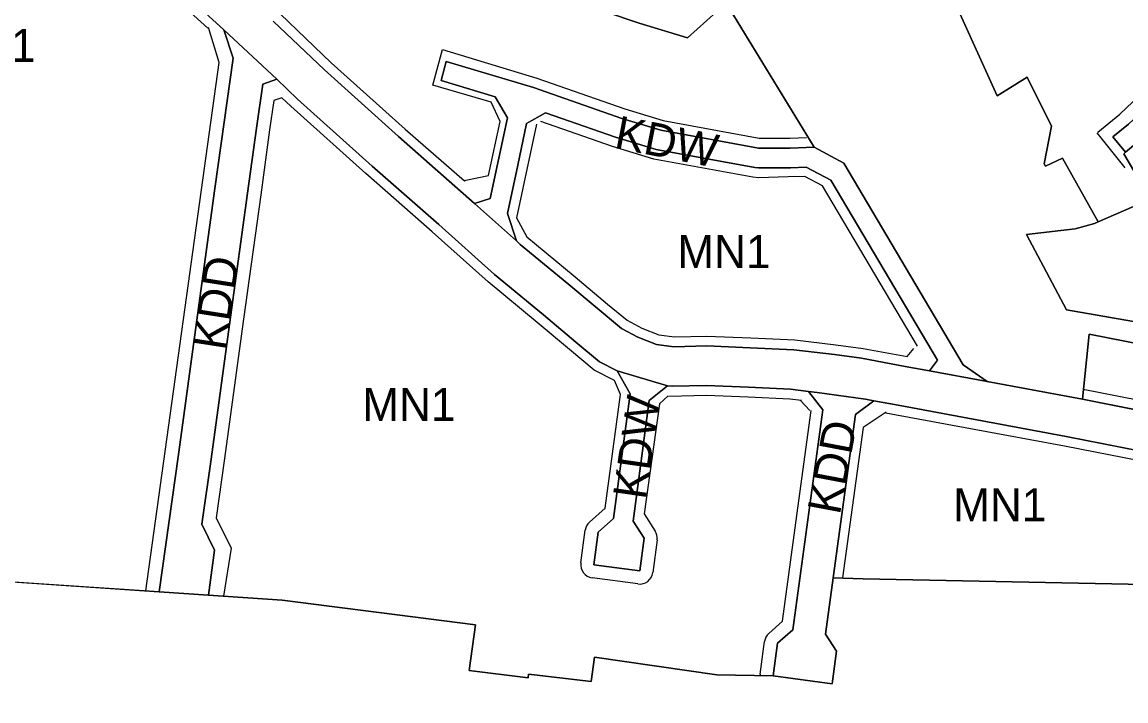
# Model space of a CAD drawing. Extents: x 7417187 to 7419415, y 5539178 to 5540826.
# Drawn here: x 7418400.2 to 7418734.7, y 5539565.4 to 5539771.1 of the extents above; entities that cross this region are included whole.
import ezdxf

# ---------------------------------------------------------------- set-up
doc = ezdxf.new("R2010")
doc.units = 0
for name, color, linetype in [('linie_rozgraniczajace', 7, 'Continuous'), ('linie_zabudowy_nieprzekraczalne', 7, 'Continuous'), ('linie_zabudowy_obowiazujace', 7, 'Continuous'), ('oznaczenia_przeznaczen', 7, 'Continuous')]:
    doc.layers.add(name, color=color, linetype=linetype)

msp = doc.modelspace()

# ---------------------------------------------------------------- linework, layer by layer
at = {"layer": 'linie_rozgraniczajace'}
for p, q in [((7418461.39, 5539768.7), (7418451.14, 5539778.14)), ((7418476.33, 5539771.33), (7418491.86, 5539756.55)), ((7418477.41, 5539753.73), (7418461.39, 5539768.7)), ((7418491.86, 5539756.55), (7418514.31, 5539736.4)), ((7418483.71, 5539747.74), (7418477.41, 5539753.73)), ((7418506.34, 5539727.43), (7418483.71, 5539747.74)), ((7418514.31, 5539736.4), (7418537.33, 5539716.11)), ((7418526.49, 5539709.72), (7418506.34, 5539727.43)), ((7418537.33, 5539716.11), (7418550, 5539704.75)), ((7418543.36, 5539694.58), (7418526.49, 5539709.72)), ((7418550, 5539704.75), (7418551.18, 5539703.68)), ((7418551.18, 5539703.68), (7418565.9, 5539691.58)), ((7418558.2, 5539682.36), (7418543.36, 5539694.58)), ((7418565.9, 5539691.58), (7418581.85, 5539678.19)), ((7418567.96, 5539674.1), (7418558.2, 5539682.36)), ((7418581.85, 5539678.19), (7418586.77, 5539675.61)), ((7418575.18, 5539668.14), (7418567.96, 5539674.1)), ((7418586.77, 5539675.61), (7418592.44, 5539673.34)), ((7418592.44, 5539673.34), (7418597.74, 5539672.7)), ((7418597.74, 5539672.7), (7418607.68, 5539672.92)), ((7418607.68, 5539672.92), (7418620.86, 5539672.39)), ((7418620.86, 5539672.39), (7418634.07, 5539671.76)), ((7418634.07, 5539671.76), (7418646.4, 5539670.32)), ((7418646.4, 5539670.32), (7418654.54, 5539669.18)), ((7418580.51, 5539665.34), (7418575.18, 5539668.14)), ((7418654.54, 5539669.18), (7418667.82, 5539666.74)), ((7418667.82, 5539666.74), (7418675.19, 5539665.37)), ((7418595.74, 5539660.85), (7418580.51, 5539665.34)), ((7418675.19, 5539665.37), (7418692.57, 5539662.15)), ((7418597.15, 5539660.69), (7418595.74, 5539660.85)), ((7418607.57, 5539660.91), (7418597.15, 5539660.69)), ((7418620.34, 5539660.4), (7418607.57, 5539660.91)), ((7418633.08, 5539659.8), (7418620.34, 5539660.4)), ((7418638.52, 5539659.16), (7418633.08, 5539659.8)), ((7418692.57, 5539662.15), (7418718.81, 5539657.28)), ((7418641.12, 5539658.85), (7418638.52, 5539659.16)), ((7418655.74, 5539656.76), (7418641.12, 5539658.85)), ((7418658.31, 5539656.29), (7418655.74, 5539656.76)), ((7418665.64, 5539654.94), (7418658.31, 5539656.29)), ((7418718.81, 5539657.28), (7418721.47, 5539656.75)), ((7418721.47, 5539656.75), (7418755.04, 5539650.17)), ((7418716.56, 5539645.49), (7418665.64, 5539654.94)), ((7418743.77, 5539640.15), (7418716.56, 5539645.49)), ((7418643.64, 5539585.58), (7418645.97, 5539602.68)), ((7418645.97, 5539602.68), (7418655.08, 5539602.38)), ((7418379.39, 5539602.6), (7418441.73, 5539598.41)), ((7418655.08, 5539602.38), (7418740.36, 5539600.67)), ((7418441.73, 5539598.41), (7418456.67, 5539597.41)), ((7418456.67, 5539597.41), (7418479.05, 5539595.91)), ((7418479.05, 5539595.91), (7418537.63, 5539588.41)), ((7418537.63, 5539588.41), (7418535.64, 5539574.6)), ((7418646.97, 5539580.4), (7418643.64, 5539585.58)), ((7418645.63, 5539570.49), (7418646.97, 5539580.4)), ((7418572.64, 5539571.27), (7418573.63, 5539578.64)), ((7418573.63, 5539578.64), (7418610.7, 5539573.29)), ((7418535.64, 5539574.6), (7418553.6, 5539572.38)), ((7418553.6, 5539572.38), (7418553.71, 5539573.49)), ((7418553.71, 5539573.49), (7418572.64, 5539571.27)), ((7418610.7, 5539573.29), (7418627.79, 5539572.92)), ((7418627.79, 5539572.92), (7418645.63, 5539570.49))]:
    msp.add_line(p, q, dxfattribs=at)
for points in [[(7418393.93, 5539842.31), (7418427.7, 5539802.79), (7418451.14, 5539778.14), (7418461.39, 5539768.7), (7418464.15, 5539760.11), (7418458.68, 5539720.6), (7418453.49, 5539682.96), (7418447.59, 5539640.03), (7418441.73, 5539598.41), (7418379.39, 5539602.6)], [(7418736.92, 5539715.13), (7418726.22, 5539710.49), (7418715.48, 5539729.82), (7418710.25, 5539727.38), (7418709.84, 5539728.16), (7418712.08, 5539739.56), (7418704.78, 5539754.37), (7418695.68, 5539748.68), (7418682.41, 5539778.05), (7418644.96, 5539813.17), (7418657.8, 5539827.5), (7418672.39, 5539827.92), (7418675.97, 5539823.68), (7418689.24, 5539814.6), (7418710.86, 5539804.53), (7418718.37, 5539803.19), (7418732.26, 5539794.78), (7418747.18, 5539783.41)], [(7418555.64, 5539781.44), (7418587.17, 5539770.77), (7418601.79, 5539766.3), (7418613.5, 5539776.82), (7418640.23, 5539733.18), (7418632.9, 5539732.88), (7418623.31, 5539732.9), (7418593.75, 5539738.28), (7418581.92, 5539741.89), (7418555.15, 5539751.21), (7418528.67, 5539759.15), (7418527.21, 5539753.33), (7418543.59, 5539748.41), (7418547.33, 5539742.09), (7418542.09, 5539717.59), (7418537.33, 5539716.11), (7418514.31, 5539736.4), (7418491.86, 5539756.55), (7418476.33, 5539771.33)], [(7418779.1, 5539665.63), (7418723.54, 5539676.5), (7418721.47, 5539656.75), (7418718.81, 5539657.28), (7418692.57, 5539662.15), (7418685.31, 5539667.23), (7418649.17, 5539728.33), (7418640.23, 5539733.18), (7418613.5, 5539776.82), (7418601.79, 5539766.3), (7418587.17, 5539770.77), (7418555.64, 5539781.44)], [(7418682.41, 5539778.05), (7418695.68, 5539748.68), (7418704.78, 5539754.37), (7418712.08, 5539739.56), (7418709.84, 5539728.16), (7418710.25, 5539727.38), (7418715.48, 5539729.82), (7418726.22, 5539710.49), (7418725.09, 5539710), (7418719.32, 5539708.39), (7418704.53, 5539706.68), (7418716.69, 5539683.83), (7418781.07, 5539672.68)], [(7418735.44, 5539740.18), (7418730.71, 5539736.26), (7418734.54, 5539731.64), (7418734.05, 5539731.09), (7418742.1, 5539717.38)], [(7418755.04, 5539650.17), (7418721.47, 5539656.75), (7418723.54, 5539676.5), (7418779.1, 5539665.63)]]:
    msp.add_lwpolyline(points, dxfattribs=at)
for points in [[(7418774.51, 5539759.77), (7418765.61, 5539759.3), (7418763.11, 5539756.96), (7418751.12, 5539746.68), (7418739.41, 5539735.68), (7418734.54, 5539731.64), (7418730.71, 5539736.26), (7418735.44, 5539740.18), (7418747.12, 5539751.15), (7418759.1, 5539761.43), (7418763.48, 5539765.38), (7418763.35, 5539770.81)], [(7418477.41, 5539753.73), (7418473.13, 5539752.27), (7418471.24, 5539738.95), (7418468.58, 5539719.25), (7418463.4, 5539681.6), (7418457.5, 5539638.66), (7418454.71, 5539618.88), (7418458.53, 5539611.01), (7418456.67, 5539597.41), (7418441.73, 5539598.41), (7418447.59, 5539640.03), (7418453.49, 5539682.96), (7418458.68, 5539720.6), (7418464.15, 5539760.11), (7418461.39, 5539768.7)], [(7418640.23, 5539733.18), (7418649.17, 5539728.33), (7418685.31, 5539667.23), (7418692.57, 5539662.15), (7418675.19, 5539665.37), (7418677.56, 5539668.57), (7418645.27, 5539723.13), (7418637.83, 5539727.08), (7418633.01, 5539726.88), (7418623.3, 5539726.9), (7418622.23, 5539726.99), (7418592.33, 5539732.44), (7418580.06, 5539736.19), (7418558.83, 5539743.58), (7418553.09, 5539740.32), (7418550.4, 5539727.75), (7418547.26, 5539713.08), (7418550, 5539704.75), (7418537.33, 5539716.11), (7418542.09, 5539717.59), (7418547.33, 5539742.09), (7418543.59, 5539748.41), (7418527.21, 5539753.33), (7418528.67, 5539759.15), (7418555.15, 5539751.21), (7418581.92, 5539741.89), (7418593.75, 5539738.28), (7418623.31, 5539732.9), (7418632.9, 5539732.88)], [(7418804.62, 5539739.12), (7418791.51, 5539718.25), (7418808.62, 5539698.53), (7418811.52, 5539682.26), (7418812.55, 5539679.73), (7418812.43, 5539674.88), (7418800.26, 5539673.95), (7418781.07, 5539672.68), (7418716.69, 5539683.83), (7418704.53, 5539706.68), (7418719.32, 5539708.39), (7418725.09, 5539710), (7418726.22, 5539710.49), (7418736.92, 5539715.13), (7418742.1, 5539717.38), (7418734.05, 5539731.09), (7418734.54, 5539731.64), (7418739.41, 5539735.68), (7418751.12, 5539746.68), (7418763.11, 5539756.96), (7418765.61, 5539759.3), (7418774.51, 5539759.77), (7418780.23, 5539755.6), (7418794.71, 5539745.18)], [(7418580.51, 5539665.34), (7418584.45, 5539658.37), (7418579.39, 5539620.65), (7418574.81, 5539616.53), (7418573.48, 5539606.62), (7418587.35, 5539604.76), (7418588.68, 5539614.67), (7418585.34, 5539619.85), (7418590.25, 5539656.44), (7418595.74, 5539660.85), (7418597.15, 5539660.69), (7418607.57, 5539660.91), (7418620.34, 5539660.4), (7418633.08, 5539659.8), (7418638.52, 5539659.16), (7418642.81, 5539653.56), (7418633.74, 5539586.93), (7418629.14, 5539582.83), (7418627.79, 5539572.92), (7418610.7, 5539573.29), (7418573.63, 5539578.64), (7418572.64, 5539571.27), (7418553.71, 5539573.49), (7418553.6, 5539572.38), (7418535.64, 5539574.6), (7418537.63, 5539588.41), (7418479.05, 5539595.91), (7418456.67, 5539597.41), (7418458.53, 5539611.01), (7418454.71, 5539618.88), (7418457.5, 5539638.66), (7418463.4, 5539681.6), (7418468.58, 5539719.25), (7418471.24, 5539738.95), (7418473.13, 5539752.27), (7418477.41, 5539753.73), (7418483.71, 5539747.74), (7418506.34, 5539727.43), (7418526.49, 5539709.72), (7418543.36, 5539694.58), (7418558.2, 5539682.36), (7418567.96, 5539674.1), (7418575.18, 5539668.14)], [(7418675.19, 5539665.37), (7418667.82, 5539666.74), (7418654.54, 5539669.18), (7418646.4, 5539670.32), (7418634.07, 5539671.76), (7418620.86, 5539672.39), (7418607.68, 5539672.92), (7418597.74, 5539672.7), (7418592.44, 5539673.34), (7418586.77, 5539675.61), (7418581.85, 5539678.19), (7418565.9, 5539691.58), (7418551.18, 5539703.68), (7418550, 5539704.75), (7418547.26, 5539713.08), (7418550.4, 5539727.75), (7418553.09, 5539740.32), (7418558.83, 5539743.58), (7418580.06, 5539736.19), (7418592.33, 5539732.44), (7418622.23, 5539726.99), (7418623.3, 5539726.9), (7418633.01, 5539726.88), (7418637.83, 5539727.08), (7418645.27, 5539723.13), (7418677.56, 5539668.57)], [(7418595.74, 5539660.85), (7418590.25, 5539656.44), (7418585.34, 5539619.85), (7418588.68, 5539614.67), (7418587.35, 5539604.76), (7418573.48, 5539606.62), (7418574.81, 5539616.53), (7418579.39, 5539620.65), (7418584.45, 5539658.37), (7418580.51, 5539665.34)], [(7418658.31, 5539656.29), (7418652.71, 5539652.14), (7418645.97, 5539602.68), (7418643.64, 5539585.58), (7418646.97, 5539580.4), (7418645.63, 5539570.49), (7418627.79, 5539572.92), (7418629.14, 5539582.83), (7418633.74, 5539586.93), (7418642.81, 5539653.56), (7418638.52, 5539659.16), (7418641.12, 5539658.85), (7418655.74, 5539656.76)], [(7418743.77, 5539640.15), (7418748.05, 5539634.12), (7418745.93, 5539614.83), (7418741.45, 5539610.61), (7418740.36, 5539600.67), (7418655.08, 5539602.38), (7418645.97, 5539602.68), (7418652.71, 5539652.14), (7418658.31, 5539656.29), (7418665.64, 5539654.94), (7418716.56, 5539645.49)]]:
    msp.add_lwpolyline(points, close=True, dxfattribs=at)
at = {"layer": 'linie_zabudowy_nieprzekraczalne'}
for points in [[(7418405.82, 5539851.39), (7418413.43, 5539842.93), (7418442.31, 5539808.75), (7418461.59, 5539788.91), (7418478.38, 5539773.52), (7418493.9, 5539758.76), (7418516.3, 5539738.65), (7418534.25, 5539722.94), (7418534.72, 5539723.11)], [(7418456.52, 5539769.2), (7418449.05, 5539775.99), (7418437.77, 5539787.6)], [(7418459.94, 5539758.79), (7418456.73, 5539769.44)], [(7418726.18, 5539737.71), (7418732.79, 5539743.18), (7418744.45, 5539754.13), (7418757.07, 5539764.94)], [(7418524.66, 5539751.99), (7418527.57, 5539762.78)], [(7418542.37, 5539746.77), (7418524.68, 5539751.96)], [(7418579.67, 5539662.49), (7418573.51, 5539665.63), (7418566.04, 5539671.8), (7418556.29, 5539680.06), (7418541.41, 5539692.31), (7418524.5, 5539707.48), (7418504.35, 5539725.19), (7418481.68, 5539745.54), (7418478.94, 5539748.15)], [(7418545.11, 5539740.97), (7418542.37, 5539746.77)], [(7418541.5, 5539724.62), (7418545.11, 5539740.97)], [(7418556.13, 5539740.16), (7418550.05, 5539711.79)], [(7418637.42, 5539724.28), (7418632.3, 5539724.18), (7418623.32, 5539723.9), (7418621.65, 5539724.05), (7418591.62, 5539729.53), (7418579.13, 5539733.34), (7418557.43, 5539740.89)], [(7418734.45, 5539726.94), (7418725.92, 5539737.5)], [(7418534.72, 5539723.11), (7418541.5, 5539724.62)], [(7418642.77, 5539721.48), (7418637.42, 5539724.28)], [(7418671.56, 5539672.82), (7418642.77, 5539721.48)], [(7418550.05, 5539711.79), (7418553.14, 5539705.96), (7418567.82, 5539693.88), (7418577.59, 5539685.6), (7418583.53, 5539680.7), (7418588.03, 5539678.34), (7418593.19, 5539676.27), (7418597.89, 5539675.71), (7418607.71, 5539675.92), (7418621, 5539675.39), (7418634.32, 5539674.76), (7418646.78, 5539673.29), (7418655.02, 5539672.15), (7418668.37, 5539669.69), (7418670.42, 5539672.15)], [(7418581.58, 5539658.18), (7418579.67, 5539662.49)], [(7418721.73, 5539659.8), (7418755.62, 5539653.11), (7418762.24, 5539651.8), (7418770.47, 5539648.04), (7418778.43, 5539642.93), (7418786.51, 5539635.79), (7418791.64, 5539629.51), (7418795, 5539601.4), (7418795.67, 5539592.17), (7418797.47, 5539566.82), (7418797.45, 5539565.35)], [(7418576.88, 5539623.74), (7418581.58, 5539658.18)], [(7418595.93, 5539657.82), (7418593.31, 5539655.39)], [(7418636.32, 5539656.4), (7418632.84, 5539656.81), (7418620.21, 5539657.41), (7418607.55, 5539657.91), (7418596.15, 5539657.58)], [(7418636.1, 5539656.42), (7418638.93, 5539653.39)], [(7418593.31, 5539655.39), (7418588.7, 5539622.03)], [(7418630.59, 5539589.49), (7418635.25, 5539623.78), (7418639.25, 5539653.35)], [(7418661.97, 5539652.9), (7418655.09, 5539648.18)], [(7418738.78, 5539638.08), (7418716, 5539642.55), (7418665.1, 5539651.99), (7418661.91, 5539652.58)], [(7418655.09, 5539648.18), (7418648.77, 5539602.63)], [(7418572.14, 5539619.52), (7418576.88, 5539623.74)], [(7418588.7, 5539622.02), (7418592.04, 5539616.84)], [(7418569.51, 5539607.16), (7418570.84, 5539617.07)], [(7418592.65, 5539614.14), (7418591.32, 5539604.23)], [(7418586.82, 5539600.8), (7418572.95, 5539602.66)], [(7418626.48, 5539585.81), (7418630.59, 5539589.49)], [(7418623.83, 5539573.46), (7418625.18, 5539583.37)]]:
    msp.add_lwpolyline(points, dxfattribs=at)
for centre, radius, start, end in [((7418574.8, 5539616.54), 4, 131.7515, 172.3466), ((7418588.76, 5539614.68), 3.92, 352.0762, 33.3855), ((7418573.49, 5539606.64), 4.01, 172.5016, 262.2902), ((7418587.36, 5539604.76), 4, 262.2403, 352.3906), ((7418629.08, 5539582.86), 3.94, 131.4023, 172.5015), ((7418628.25, 5539572.93), 4.45, 173.2004, 178.6284)]:
    msp.add_arc(centre, radius, start, end, dxfattribs=at)
at = {"layer": 'linie_zabudowy_obowiazujace'}
for points in [[(7418527.57, 5539762.78), (7418556.18, 5539754.03)], [(7418437.73, 5539598.68), (7418459.94, 5539758.79)], [(7418556.14, 5539754.05), (7418582.86, 5539744.75), (7418594.46, 5539741.21), (7418623.5, 5539735.92)], [(7418476.47, 5539747.27), (7418475.21, 5539738.4), (7418472.55, 5539718.71), (7418467.36, 5539681.05), (7418461.46, 5539638.11), (7418459.03, 5539620.83)], [(7418478.94, 5539748.15), (7418476.47, 5539747.27)], [(7418623.67, 5539735.9), (7418632.84, 5539735.88), (7418637.88, 5539736.09)], [(7418459.03, 5539620.83), (7418463.54, 5539611.65)], [(7418463.54, 5539611.65), (7418461.25, 5539597.1)]]:
    msp.add_lwpolyline(points, dxfattribs=at)

# ---------------------------------------------------------------- texts
at = {"layer": 'oznaczenia_przeznaczen'}
for p in [(7418376.1, 5539759.01), (7418598.74, 5539696.51), (7418503.3, 5539650.16), (7418682.31, 5539619.78)]:
    msp.add_text('MN1', height=10, dxfattribs=at).set_placement(p)
for s, rotation, p in [('KDW', 348.8681, (7418579.31, 5539732.97)), ('KDD', 81.1583, (7418461.69, 5539671.33)), ('KDW', 81.8816, (7418589.11, 5539626.11)), ('KDD', 79.2929, (7418647.95, 5539621.48))]:
    msp.add_text(s, height=10, rotation=rotation, dxfattribs=at).set_placement(p)

doc.saveas('drawing.dxf')
